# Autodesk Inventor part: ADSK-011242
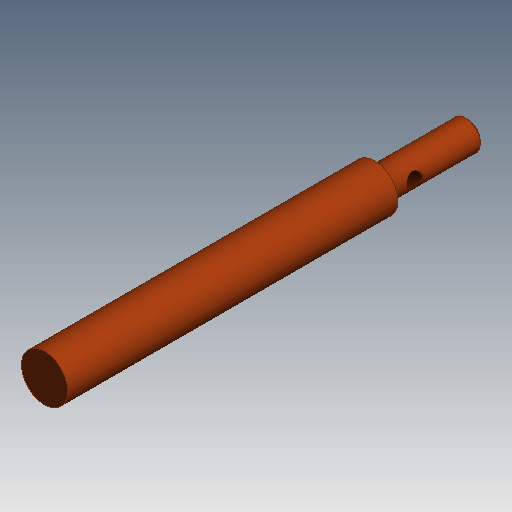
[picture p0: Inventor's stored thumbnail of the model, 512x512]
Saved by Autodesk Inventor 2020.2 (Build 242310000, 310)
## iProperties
Created: 2000-10
Part Number: ADSK-011242
Document SubType Name: Modeling
Designer: wymerj
Material: Générique
Density: 1 g/cm^3
Sheet Metal Rule: Standard
Appearance: Metal-Copper
Mass: 42.7166 g
Surface Area: 102.913 cm^2
Volume: 42.7166 cm^3
Control State: 0
Master: False
Checked Out: False
Shininess: 0.0
Length Units: 11272
Angle Units: 11279
Time Units: 11290
Mass Units: 11286
Length Display Precision: 3
Angle Display Precision: 2
Compacted: True
Dimensions: 0,8x6,8x0,8 in
Mass: 0,094 lb
VLT_Material: Generic
Density: 0.0
Volumn: 0.0
Area: 0.0
PropertySet Name: Model Information
Author: wymerj
Revision Number: -
Title: ADSK-011242
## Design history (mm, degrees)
node "Extrusion1" dims "d0" = 38.1, "d1" = 0
node "Extrusion3" dims "d7" = 135.6614, "d8" = 0
node "Chamfer1" dims "d9" = 0.762, "d10" = 0.762, "d15" = 45 deg
workaxis "Work Axis1"
workplane "Work Plane1"
node "Extrusion4" dims "d12" = 25.4, "d13" = 0
node "Solide1"
node "Corps solides"
node "Corps surfaciques"
sketch "Sketch1"
  geometry: C1 r 6.668 at (-15.24, 0) reference; C2 r 6.096 at (-15.24, 0)
  constraints: 1 centre point, 1 coincident
  dimensions: "d5" = 12.192 diameter of C2
sketch "Sketch3"
  geometry: C1 r 6.096 at (0, 0) reference; C2 r 9.525 at (0, 0)
  constraints: 1 centre point, 1 coincident
  dimensions: "d6" = 19.05 diameter of C2
sketch "Sketch4"
  geometry: C1 r 3.239 at (0, -10.287)
  constraints: 1 centre point
  dimensions: "d14" = 6.477 diameter of C1
other parameters: "Thickness" = 3.048, "BendRadius" = 3.048 (= Thickness), "BendReliefWidth" = 3.048 (= Thickness), "BendReliefDepth" = 1.524 (= 0.5 x Thickness), "CornerReliefSize" = 6.858 (= 2.25 x Thickness), "SeamGap" = 0.00508, "MinimumRemnant" = 6.096 (= 2 x Thickness), "d11" = 0, "TransitionRadius" = 3.048 (= BendRadius), "TailleRayonJacobi" = 3.048 (= Thickness), "TailleJeu" = 3.048 (= Thickness)
